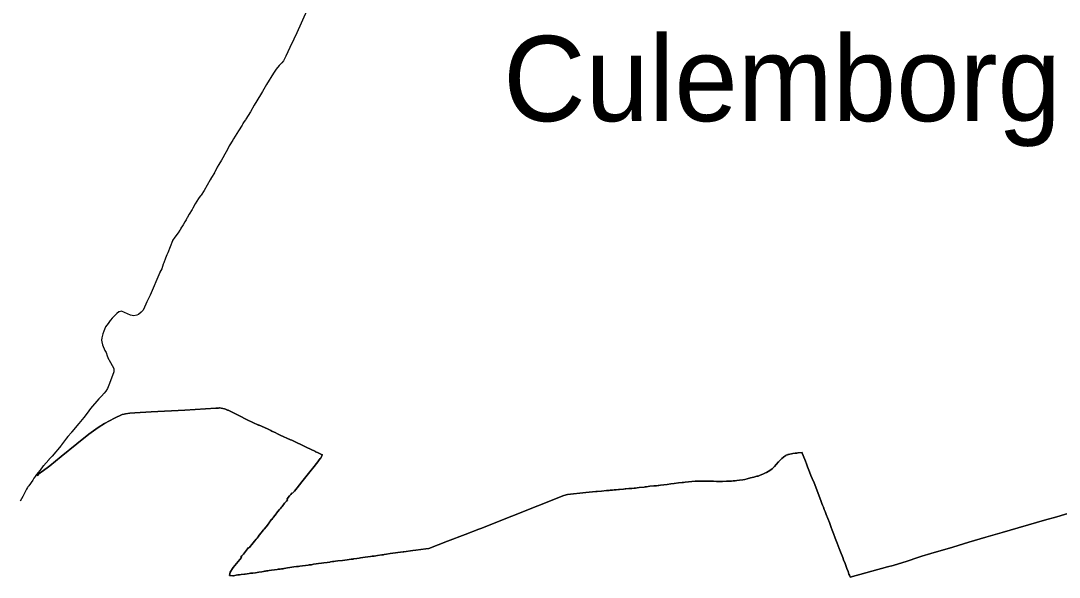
# Model space of a CAD drawing. Extents: x 113371 to 291721, y 393993 to 520143.
# Drawn here: x 138045 to 144134, y 436828 to 440092 of the extents above; entities that cross this region are included whole.
import ezdxf

# ---------------------------------------------------------------- set-up
doc = ezdxf.new("R2010")
doc.units = 0
doc.layers.add('Default', color=7, linetype='Continuous')
doc.layers.add('plaatsnamen', color=7, linetype='Continuous')

msp = doc.modelspace()

# ---------------------------------------------------------------- linework, layer by layer
at = {"layer": 'Default'}
for points in [[(139722.235625, 440152.3025), (139662.915625, 440021.2725), (139645.085625, 439984.0625), (139622.425625, 439935.0425), (139599.285625, 439884.5025), (139589.075625, 439864.6125), (139584.495625, 439857.6125), (139576.305625, 439845.1125), (139573.485625, 439843.1825), (139569.165625, 439840.2225), (139559.865625, 439830.6425), (139542.355625, 439808.3625), (139526.855625, 439785.1325), (139486.425625, 439718.1125), (139462.005625, 439677.6425), (139450.355625, 439658.4625), (139413.485625, 439597.7025), (139391.145625, 439558.9425), (139365.325625, 439514.1325), (139363.095625, 439510.2725), (139355.395625, 439500.4825), (139347.825625, 439488.7225), (139347.305625, 439487.7525), (139343.085625, 439479.8825), (139322.325625, 439445.6325), (139292.015625, 439399.2025), (139291.255625, 439397.6825), (139287.845625, 439390.9925), (139267.355625, 439357.7225), (139260.695625, 439345.0625), (139249.415625, 439323.5825)], [(139249.415625, 439323.5825), (139241.105625, 439309.1525), (139229.465625, 439288.9325), (139221.445625, 439274.9925), (139205.915625, 439248.5725), (139197.465625, 439234.1825), (139183.105625, 439205.0225), (139181.465625, 439202.3325), (139180.005625, 439199.9625), (139162.875625, 439172.0725), (139161.585625, 439169.9725), (139160.625625, 439168.4325), (139154.835625, 439158.2925), (139137.505625, 439127.9725), (139119.505625, 439097.3625), (139101.915625, 439069.7725), (139098.095625, 439064.9125), (139090.885625, 439054.6225), (139087.955625, 439049.0825), (139077.005625, 439033.2525), (139067.215625, 439018.0925), (139054.615625, 438992.8825), (139049.145625, 438984.5825), (139032.805625, 438958.2025), (139020.945625, 438936.4125), (139019.385625, 438933.3925), (139014.325625, 438925.1925), (139006.725625, 438912.4925), (138996.595625, 438896.1525), (138988.945625, 438883.4525), (138987.685625, 438881.3525), (138984.035625, 438875.2125), (138983.805625, 438874.7425), (138983.255625, 438873.8225), (138978.765625, 438864.5025), (138978.615625, 438864.1925), (138978.325625, 438863.6125), (138967.695625, 438848.6625)], [(138967.695625, 438848.6625), (138949.055625, 438822.4525), (138934.825625, 438802.4325), (138934.755625, 438802.2725), (138906.345625, 438731.2225), (138901.775625, 438719.2025), (138901.455625, 438718.3525), (138894.315625, 438699.6225), (138883.985625, 438672.5125), (138880.695625, 438663.8825), (138871.095625, 438637.9325), (138861.275625, 438617.9325), (138861.105625, 438617.5825), (138860.285625, 438615.6725), (138803.145625, 438483.4925), (138784.915625, 438443.9025), (138784.385625, 438442.7425), (138778.765625, 438430.5425), (138778.755625, 438430.5225), (138778.535625, 438430.0425), (138761.915625, 438393.9325), (138750.095625, 438383.0225), (138735.325625, 438369.3625), (138725.695625, 438364.9125), (138708.335625, 438361.4125), (138687.755625, 438366.2725), (138636.075625, 438389.1625), (138622.285625, 438384.5725), (138620.575625, 438383.9925), (138608.915625, 438374.7725), (138580.305625, 438346.8925), (138571.265625, 438336.5125), (138569.625625, 438334.6325), (138556.445625, 438316.5725), (138542.145625, 438296.9725), (138536.465625, 438282.1725), (138532.325625, 438271.3825), (138526.355625, 438255.8225)], [(138526.355625, 438255.8225), (138520.395625, 438232.2525), (138519.195625, 438219.2725), (138521.035625, 438209.6325), (138524.445625, 438191.6125), (138524.675625, 438191.0225), (138536.965625, 438158.2925), (138545.735625, 438146.9025), (138551.865625, 438126.7225), (138559.645625, 438107.7225), (138560.545625, 438106.1625), (138591.595625, 438052.3825), (138589.825625, 438032.7525), (138582.285625, 438011.5425), (138561.915625, 437954.2525), (138553.575625, 437935.1125), (138544.325625, 437920.0625), (138533.175625, 437906.9725), (138518.395625, 437889.6125), (138502.835625, 437873.5425), (138454.415625, 437817.1625), (138433.285625, 437789.7025), (138413.945625, 437764.5825), (138385.055625, 437730.5725), (138344.185625, 437680.4725), (138342.955625, 437678.0425), (138342.395625, 437676.9325), (138320.805625, 437653.1125), (138313.225625, 437643.0025), (138284.565625, 437604.7825), (138282.215625, 437601.6325), (138228.385625, 437538.4425), (138226.775625, 437536.5525), (138210.275625, 437518.2425), (138209.035625, 437516.8625), (138178.165625, 437480.7225), (138177.075625, 437481.6125), (138176.585625, 437480.9525)], [(138176.585625, 437480.9525), (138158.185625, 437456.6125), (138157.015625, 437455.0625), (138146.125625, 437442.5225), (138137.345625, 437430.4325), (138137.865625, 437430.1825), (138145.485625, 437425.4525), (138147.875625, 437427.5725), (138147.905625, 437430.2225), (138160.825625, 437443.1125), (138170.195625, 437447.5225), (138216.025625, 437482.0825), (138281.535625, 437535.3325), (138374.445625, 437611.1125), (138444.845625, 437667.4425), (138498.095625, 437705.8525), (138536.495625, 437729.3625), (138594.845625, 437760.8025), (138640.165625, 437781.9125), (138650.845625, 437784.1325), (138659.835625, 437786.9425), (138683.755625, 437790.5025), (138713.755625, 437791.8525), (138809.415625, 437798.8325), (139007.705625, 437809.0025), (139187.895625, 437819.0925), (139204.445625, 437819.1025), (139208.455625, 437821.3325), (139209.285625, 437821.7925), (139230.665625, 437817.7825), (139239.525625, 437814.9325), (139245.135625, 437814.5225), (139246.215625, 437814.0425), (139253.365625, 437810.3525), (139256.185625, 437808.8925), (139260.295625, 437807.1125), (139276.165625, 437800.6825), (139281.175625, 437798.4325)], [(139491.545625, 437697.6225), (139442.755625, 437719.3925), (139439.575625, 437720.6925), (139437.445625, 437721.5725), (139435.355625, 437722.4325), (139431.465625, 437724.0325), (139414.035625, 437731.4925), (139397.975625, 437738.9425), (139397.605625, 437739.1125), (139381.145625, 437746.7125), (139379.335625, 437747.5025), (139377.305625, 437748.4125), (139319.735625, 437779.1925), (139319.025625, 437779.5425), (139307.485625, 437785.1825), (139292.375625, 437792.9425), (139284.035625, 437797.0325), (139281.175625, 437798.4325), (139276.165625, 437800.6825), (139260.295625, 437807.1125), (139256.185625, 437808.8925), (139253.365625, 437810.3525), (139246.215625, 437814.0425), (139245.135625, 437814.5225), (139239.525625, 437814.9325), (139230.665625, 437817.7825), (139209.285625, 437821.7925), (139208.455625, 437821.3325), (139204.445625, 437819.1025), (139187.895625, 437819.0925), (139007.705625, 437809.0025), (138809.415625, 437798.8325), (138713.755625, 437791.8525), (138683.755625, 437790.5025), (138659.835625, 437786.9425), (138650.845625, 437784.1325), (138640.165625, 437781.9125), (138594.845625, 437760.8025)], [(138594.845625, 437760.8025), (138536.495625, 437729.3625), (138498.095625, 437705.8525), (138444.845625, 437667.4425), (138374.445625, 437611.1125), (138281.535625, 437535.3325), (138216.025625, 437482.0825), (138170.195625, 437447.5225), (138160.825625, 437443.1125), (138147.905625, 437430.2225), (138147.875625, 437427.5725), (138145.485625, 437425.4525), (138137.865625, 437430.1825), (138137.345625, 437430.4325), (138137.275625, 437430.3425), (138131.435625, 437422.1825), (138131.275625, 437421.9625), (138131.105625, 437421.7325), (138122.325625, 437409.6425), (138116.915625, 437400.3925), (138114.705625, 437397.2925), (138091.295625, 437364.3625), (138087.195625, 437358.5925), (138084.415625, 437354.6825), (138077.715625, 437343.8825), (138068.305625, 437325.3625), (138057.015625, 437300.8825), (138041.445625, 437274.9325)], [(139281.175625, 437798.4325), (139284.035625, 437797.0325), (139292.375625, 437792.9425), (139307.485625, 437785.1825), (139319.025625, 437779.5425), (139319.735625, 437779.1925), (139377.305625, 437748.4125), (139379.335625, 437747.5025), (139381.145625, 437746.7125), (139397.605625, 437739.1125), (139397.975625, 437738.9425), (139414.035625, 437731.4925), (139431.465625, 437724.0325), (139435.355625, 437722.4325), (139437.445625, 437721.5725), (139439.575625, 437720.6925), (139442.755625, 437719.3925), (139491.545625, 437697.6225), (139506.805625, 437690.8125), (139510.845625, 437688.5725), (139517.675625, 437685.1825), (139520.875625, 437683.5925), (139536.375625, 437676.4325), (139550.415625, 437669.4525), (139566.475625, 437661.5825), (139626.365625, 437633.0525), (139626.525625, 437633.0325), (139634.275625, 437631.6625), (139635.235625, 437631.1825), (139718.195625, 437590.4525), (139772.165625, 437565.1125), (139773.975625, 437564.2525), (139784.775625, 437559.1825), (139808.905625, 437547.8525), (139813.645625, 437545.6325), (139810.985625, 437541.3925), (139810.465625, 437540.5625), (139807.645625, 437536.0525)], [(139607.305625, 437287.3425), (139621.485625, 437304.9725), (139628.365625, 437314.0825), (139634.125625, 437321.8425), (139635.395625, 437323.4125), (139638.885625, 437320.4225), (139647.175625, 437330.0325), (139649.065625, 437332.0725), (139665.285625, 437351.8625), (139692.975625, 437387.7525), (139716.715625, 437417.1825), (139748.395625, 437456.6925), (139757.735625, 437468.6125), (139786.585625, 437505.1125), (139791.395625, 437511.2125), (139801.375625, 437524.3725), (139803.445625, 437526.6125), (139807.645625, 437536.0525), (139810.465625, 437540.5625), (139810.985625, 437541.3925), (139813.645625, 437545.6325), (139808.905625, 437547.8525), (139784.775625, 437559.1825), (139773.975625, 437564.2525), (139772.165625, 437565.1125), (139718.195625, 437590.4525), (139635.235625, 437631.1825), (139634.275625, 437631.6625), (139626.525625, 437633.0325), (139626.365625, 437633.0525), (139566.475625, 437661.5825), (139550.415625, 437669.4525), (139536.375625, 437676.4325), (139520.875625, 437683.5925), (139517.675625, 437685.1825), (139510.845625, 437688.5725), (139506.805625, 437690.8125), (139491.545625, 437697.6225)], [(139807.645625, 437536.0525), (139803.445625, 437526.6125), (139801.375625, 437524.3725), (139791.395625, 437511.2125), (139786.585625, 437505.1125), (139757.735625, 437468.6125), (139748.395625, 437456.6925), (139716.715625, 437417.1825), (139692.975625, 437387.7525), (139665.285625, 437351.8625), (139649.065625, 437332.0725), (139647.175625, 437330.0325), (139638.885625, 437320.4225), (139635.395625, 437323.4125), (139634.125625, 437321.8425), (139628.365625, 437314.0825), (139621.485625, 437304.9725), (139607.305625, 437287.3425), (139606.595625, 437286.3925), (139608.835625, 437282.5825), (139602.235625, 437274.6825), (139602.185625, 437274.6225), (139596.695625, 437267.7525), (139591.995625, 437261.8825), (139577.715625, 437243.8125), (139573.885625, 437239.3925), (139568.105625, 437231.9025), (139562.985625, 437225.5525), (139551.225625, 437211.0725), (139535.805625, 437191.5125), (139525.465625, 437179.0125), (139522.705625, 437175.0525), (139520.795625, 437172.4325), (139516.515625, 437167.0825), (139515.735625, 437166.0625), (139507.735625, 437155.9225), (139505.685625, 437153.3725), (139499.325625, 437144.7025)], [(142203.435625, 437391.3625), (142213.025625, 437392.4925), (142222.935625, 437392.9225), (142233.605625, 437393.7325), (142244.365625, 437395.3525), (142259.665625, 437397.1425), (142278.085625, 437399.4025), (142289.815625, 437401.6825), (142304.275625, 437405.3025), (142324.045625, 437410.4225), (142342.505625, 437415.3525), (142354.475625, 437418.1525), (142361.195625, 437420.1125), (142364.805625, 437420.7525), (142367.985625, 437421.3725), (142371.935625, 437422.7125), (142380.815625, 437426.0125), (142395.505625, 437432.9025), (142400.435625, 437434.9025), (142411.655625, 437440.6025), (142417.015625, 437443.2525), (142427.765625, 437448.7425), (142437.885625, 437454.9625), (142449.855625, 437463.1625), (142457.545625, 437470.4825), (142464.255625, 437477.9625), (142474.155625, 437488.5625), (142488.775625, 437504.3625), (142499.865625, 437516.0325), (142508.345625, 437525.0625), (142516.575625, 437532.7825), (142519.915625, 437535.1825), (142530.675625, 437542.9625), (142532.355625, 437543.9625), (142533.615625, 437544.3725), (142540.305625, 437546.2925), (142543.435625, 437547.6525), (142546.315625, 437548.3625)], [(142742.695625, 437261.3225), (142736.025625, 437278.7425), (142696.125625, 437380.9325), (142684.425625, 437407.4425), (142677.495625, 437425.1025), (142669.885625, 437446.0125), (142658.455625, 437475.9625), (142651.615625, 437493.7425), (142645.765625, 437507.9925), (142632.375625, 437541.3725), (142627.355625, 437556.4925), (142626.215625, 437559.4125), (142602.785625, 437557.0025), (142600.735625, 437556.8625), (142595.775625, 437556.1525), (142585.595625, 437554.9725), (142572.625625, 437553.4425), (142564.075625, 437552.0825), (142553.895625, 437550.2225), (142546.315625, 437548.3625), (142543.435625, 437547.6525), (142540.305625, 437546.2925), (142533.615625, 437544.3725), (142532.355625, 437543.9625), (142530.675625, 437542.9625), (142519.915625, 437535.1825), (142516.575625, 437532.7825), (142508.345625, 437525.0625), (142499.865625, 437516.0325), (142488.775625, 437504.3625), (142474.155625, 437488.5625), (142464.255625, 437477.9625), (142457.545625, 437470.4825), (142449.855625, 437463.1625), (142437.885625, 437454.9625), (142427.765625, 437448.7425), (142417.015625, 437443.2525), (142411.655625, 437440.6025)], [(142546.315625, 437548.3625), (142553.895625, 437550.2225), (142564.075625, 437552.0825), (142572.625625, 437553.4425), (142585.595625, 437554.9725), (142595.775625, 437556.1525), (142600.735625, 437556.8625), (142602.785625, 437557.0025), (142626.215625, 437559.4125), (142627.355625, 437556.4925), (142632.375625, 437541.3725), (142645.765625, 437507.9925), (142651.615625, 437493.7425), (142658.455625, 437475.9625), (142669.885625, 437446.0125), (142677.495625, 437425.1025), (142684.425625, 437407.4425), (142696.125625, 437380.9325), (142736.025625, 437278.7425), (142742.695625, 437261.3225), (142746.695625, 437250.8225), (142751.195625, 437239.1625), (142756.565625, 437225.3425), (142761.085625, 437213.6025), (142768.175625, 437195.4725), (142786.335625, 437149.4425), (142794.625625, 437124.7725), (142796.695625, 437119.5525), (142802.605625, 437104.0225), (142810.345625, 437084.0925), (142820.955625, 437056.4725), (142831.845625, 437028.6725), (142838.715625, 437011.4025), (142844.505625, 436996.8525), (142851.935625, 436977.4925), (142864.375625, 436944.6225), (142869.725625, 436930.6425), (142877.945625, 436908.3525)], [(142411.655625, 437440.6025), (142400.435625, 437434.9025), (142395.505625, 437432.9025), (142380.815625, 437426.0125), (142371.935625, 437422.7125), (142367.985625, 437421.3725), (142364.805625, 437420.7525), (142361.195625, 437420.1125), (142354.475625, 437418.1525), (142342.505625, 437415.3525), (142324.045625, 437410.4225), (142304.275625, 437405.3025), (142289.815625, 437401.6825), (142278.085625, 437399.4025), (142259.665625, 437397.1425), (142244.365625, 437395.3525), (142233.605625, 437393.7325), (142222.935625, 437392.9225), (142213.025625, 437392.4925), (142203.435625, 437391.3625), (142195.815625, 437390.9525), (142191.535625, 437390.9525), (142185.965625, 437390.8225), (142183.325625, 437390.8925), (142158.715625, 437390.1825), (142157.475625, 437390.0425), (142152.665625, 437390.0525), (142143.765625, 437390.1025), (142125.085625, 437390.0425), (142106.675625, 437390.6325), (142076.945625, 437391.6525), (142069.865625, 437391.9825), (142050.735625, 437391.9625), (142031.325625, 437391.6325), (142013.855625, 437391.4425), (141999.255625, 437391.0425), (141979.495625, 437389.4925), (141960.825625, 437387.7725)], [(141960.825625, 437387.7725), (141941.125625, 437385.6125), (141931.535625, 437384.3825), (141922.255625, 437382.9625), (141901.615625, 437380.9525), (141876.915625, 437377.9225), (141857.465625, 437375.9825), (141834.155625, 437372.6925), (141816.155625, 437370.3025), (141796.975625, 437368.0525), (141785.935625, 437366.5125), (141781.745625, 437365.7925), (141773.055625, 437364.8025), (141756.715625, 437363.2325), (141733.425625, 437361.3725), (141713.365625, 437359.0025), (141705.695625, 437357.4325), (141699.305625, 437356.7025), (141670.205625, 437353.4125), (141659.475625, 437351.9925), (141649.175625, 437351.1125), (141641.715625, 437350.7025), (141627.125625, 437349.2925), (141610.085625, 437347.8025), (141592.815625, 437346.1825), (141588.185625, 437346.0125), (141578.275625, 437345.4925), (141556.185625, 437343.0025), (141550.505625, 437342.6325), (141536.765625, 437341.5725), (141524.525625, 437340.4325), (141514.575625, 437339.2925), (141500.425625, 437338.0125), (141494.585625, 437337.4025), (141479.455625, 437335.8325), (141450.145625, 437333.1925), (141424.645625, 437330.9925), (141422.075625, 437330.7525)], [(141659.475625, 437351.9925), (141670.205625, 437353.4125), (141699.305625, 437356.7025), (141705.695625, 437357.4325), (141713.365625, 437359.0025), (141733.425625, 437361.3725), (141756.715625, 437363.2325), (141773.055625, 437364.8025), (141781.745625, 437365.7925), (141785.935625, 437366.5125), (141796.975625, 437368.0525), (141816.155625, 437370.3025), (141834.155625, 437372.6925), (141857.465625, 437375.9825), (141876.915625, 437377.9225), (141901.615625, 437380.9525), (141922.255625, 437382.9625), (141931.535625, 437384.3825), (141941.125625, 437385.6125), (141960.825625, 437387.7725), (141979.495625, 437389.4925), (141999.255625, 437391.0425), (142013.855625, 437391.4425), (142031.325625, 437391.6325), (142050.735625, 437391.9625), (142069.865625, 437391.9825), (142076.945625, 437391.6525), (142106.675625, 437390.6325), (142125.085625, 437390.0425), (142143.765625, 437390.1025), (142152.665625, 437390.0525), (142157.475625, 437390.0425), (142158.715625, 437390.1825), (142183.325625, 437390.8925), (142185.965625, 437390.8225), (142191.535625, 437390.9525), (142195.815625, 437390.9525), (142203.435625, 437391.3625)], [(141422.075625, 437330.7525), (141417.765625, 437330.3725), (141357.755625, 437324.9825), (141250.015625, 437313.3225), (141228.905625, 437308.0425), (140772.325625, 437126.5325), (140747.615625, 437116.6025), (140730.645625, 437109.7625), (140651.455625, 437078.7925), (140547.495625, 437039.6925), (140438.205625, 436996.5625), (140419.785625, 436993.6625), (140361.615625, 436986.4325), (140344.075625, 436984.2225), (140290.125625, 436977.4225), (140287.595625, 436977.1025), (140210.325625, 436966.9425), (140189.515625, 436963.3325), (140176.135625, 436961.0125), (140171.755625, 436960.2525), (140162.985625, 436958.7425), (140162.825625, 436958.7125), (140136.965625, 436955.1225), (140117.115625, 436952.1425), (140111.925625, 436951.2725), (140110.145625, 436951.3425), (140104.545625, 436950.8425), (140096.035625, 436949.5725), (140064.715625, 436945.2225), (140037.725625, 436942.0425), (140029.215625, 436940.6525), (140028.935625, 436940.6125), (140015.515625, 436938.2325), (139998.415625, 436935.8825), (139995.015625, 436935.3325), (139994.735625, 436934.9625), (139982.405625, 436933.4725), (139959.305625, 436930.2725)], [(140171.755625, 436960.2525), (140176.135625, 436961.0125), (140189.515625, 436963.3325), (140210.325625, 436966.9425), (140287.595625, 436977.1025), (140290.125625, 436977.4225), (140344.075625, 436984.2225), (140361.615625, 436986.4325), (140419.785625, 436993.6625), (140438.205625, 436996.5625), (140547.495625, 437039.6925), (140651.455625, 437078.7925), (140730.645625, 437109.7625), (140747.615625, 437116.6025), (140772.325625, 437126.5325), (141228.905625, 437308.0425), (141250.015625, 437313.3225), (141357.755625, 437324.9825), (141417.765625, 437330.3725), (141422.075625, 437330.7525), (141424.645625, 437330.9925), (141450.145625, 437333.1925), (141479.455625, 437335.8325), (141494.585625, 437337.4025), (141500.425625, 437338.0125), (141514.575625, 437339.2925), (141524.525625, 437340.4325), (141536.765625, 437341.5725), (141550.505625, 437342.6325), (141556.185625, 437343.0025), (141578.275625, 437345.4925), (141588.185625, 437346.0125), (141592.815625, 437346.1825), (141610.085625, 437347.8025), (141627.125625, 437349.2925), (141641.715625, 437350.7025), (141649.175625, 437351.1125), (141659.475625, 437351.9925)], [(139380.675625, 437001.4925), (139383.135625, 437000.2525), (139385.665625, 437003.3325), (139390.085625, 437008.4525), (139399.575625, 437020.4025), (139414.975625, 437039.1625), (139425.355625, 437051.2025), (139429.915625, 437056.0025), (139430.665625, 437057.0525), (139436.515625, 437065.1325), (139443.095625, 437074.4525), (139454.715625, 437088.5725), (139460.985625, 437096.6725), (139468.625625, 437105.6625), (139472.325625, 437110.4825), (139483.205625, 437123.8525), (139497.255625, 437141.9825), (139499.325625, 437144.7025), (139505.685625, 437153.3725), (139507.735625, 437155.9225), (139515.735625, 437166.0625), (139516.515625, 437167.0825), (139520.795625, 437172.4325), (139522.705625, 437175.0525), (139525.465625, 437179.0125), (139535.805625, 437191.5125), (139551.225625, 437211.0725), (139562.985625, 437225.5525), (139568.105625, 437231.9025), (139573.885625, 437239.3925), (139577.715625, 437243.8125), (139591.995625, 437261.8825), (139596.695625, 437267.7525), (139602.185625, 437274.6225), (139602.235625, 437274.6825), (139608.835625, 437282.5825), (139606.595625, 437286.3925), (139607.305625, 437287.3425)], [(144048.015625, 437162.7725), (143799.615625, 437090.2725), (143704.425625, 437063.7225), (143603.325625, 437032.9225), (143509.605625, 437003.6325), (143381.255625, 436967.6225), (143328.245625, 436952.1125), (143286.705625, 436938.0725), (143259.005625, 436928.5125), (143236.205625, 436919.9425), (143216.565625, 436913.9625), (143159.305625, 436897.5825), (143127.295625, 436888.9825), (142908.145625, 436827.9725), (142907.615625, 436829.3925), (142903.695625, 436840.0925), (142900.965625, 436846.4025), (142895.605625, 436860.7025), (142888.835625, 436880.1525), (142877.945625, 436908.3525), (142869.725625, 436930.6425), (142864.375625, 436944.6225), (142851.935625, 436977.4925), (142844.505625, 436996.8525), (142838.715625, 437011.4025), (142831.845625, 437028.6725), (142820.955625, 437056.4725), (142810.345625, 437084.0925), (142802.605625, 437104.0225), (142796.695625, 437119.5525), (142794.625625, 437124.7725), (142786.335625, 437149.4425), (142768.175625, 437195.4725), (142761.085625, 437213.6025), (142756.565625, 437225.3425), (142751.195625, 437239.1625), (142746.695625, 437250.8225), (142742.695625, 437261.3225)], [(142877.945625, 436908.3525), (142888.835625, 436880.1525), (142895.605625, 436860.7025), (142900.965625, 436846.4025), (142903.695625, 436840.0925), (142907.615625, 436829.3925), (142908.145625, 436827.9725), (143127.295625, 436888.9825), (143159.305625, 436897.5825), (143216.565625, 436913.9625), (143236.205625, 436919.9425), (143259.005625, 436928.5125), (143286.705625, 436938.0725), (143328.245625, 436952.1125), (143381.255625, 436967.6225), (143509.605625, 437003.6325), (143603.325625, 437032.9225), (143704.425625, 437063.7225), (143799.615625, 437090.2725), (144048.015625, 437162.7725), (144119.155625, 437182.8025), (144208.925625, 437210.3025)], [(144208.925625, 437210.3025), (144119.155625, 437182.8025), (144048.015625, 437162.7725)], [(139499.325625, 437144.7025), (139497.255625, 437141.9825), (139483.205625, 437123.8525), (139472.325625, 437110.4825), (139468.625625, 437105.6625), (139460.985625, 437096.6725), (139454.715625, 437088.5725), (139443.095625, 437074.4525), (139436.515625, 437065.1325), (139430.665625, 437057.0525), (139429.915625, 437056.0025), (139425.355625, 437051.2025), (139414.975625, 437039.1625), (139399.575625, 437020.4025), (139390.085625, 437008.4525), (139385.665625, 437003.3325), (139383.135625, 437000.2525), (139380.675625, 437001.4925), (139350.755625, 436963.9625), (139344.015625, 436955.5125), (139341.755625, 436952.6625), (139335.985625, 436945.4325), (139338.445625, 436943.5025), (139289.755625, 436885.1325), (139272.925625, 436858.2925), (139268.325625, 436838.0425), (139268.575625, 436838.0225), (139288.575625, 436836.3125), (139290.515625, 436836.5825), (139292.935625, 436836.9325), (139308.695625, 436840.3825), (139316.735625, 436841.5125), (139321.175625, 436841.9825), (139324.665625, 436842.2925), (139326.235625, 436842.4725), (139326.935625, 436842.4925)], [(139514.785625, 436868.9925), (139501.965625, 436867.0925), (139494.205625, 436866.0225), (139485.475625, 436864.8325), (139480.255625, 436864.1325), (139476.595625, 436863.5725), (139474.735625, 436863.2625), (139467.245625, 436861.8925), (139457.725625, 436860.4525), (139441.485625, 436857.7725), (139421.875625, 436854.6925), (139404.845625, 436852.4725), (139401.035625, 436852.1125), (139392.855625, 436851.0525), (139383.385625, 436849.8825), (139361.515625, 436846.7725), (139358.185625, 436846.0225), (139356.585625, 436845.5225), (139338.185625, 436843.6725), (139326.935625, 436842.4925), (139326.235625, 436842.4725), (139324.665625, 436842.2925), (139321.175625, 436841.9825), (139316.735625, 436841.5125), (139308.695625, 436840.3825), (139292.935625, 436836.9325), (139290.515625, 436836.5825), (139288.575625, 436836.3125), (139268.575625, 436838.0225), (139268.325625, 436838.0425), (139272.925625, 436858.2925), (139289.755625, 436885.1325), (139338.445625, 436943.5025), (139335.985625, 436945.4325), (139341.755625, 436952.6625), (139344.015625, 436955.5125), (139350.755625, 436963.9625), (139380.675625, 437001.4925)], [(139715.225625, 436897.5225), (139729.505625, 436899.5825), (139735.945625, 436900.5925), (139737.615625, 436900.7325), (139749.035625, 436901.6525), (139761.195625, 436903.7225), (139777.345625, 436906.3025), (139791.125625, 436908.3125), (139807.755625, 436910.5425), (139822.565625, 436912.5425), (139840.725625, 436914.9725), (139857.075625, 436917.2825), (139861.895625, 436918.1125), (139873.175625, 436919.3625), (139881.165625, 436920.3925), (139891.015625, 436921.3025), (139903.675625, 436923.2925), (139932.105625, 436926.1125), (139944.865625, 436927.5225), (139959.305625, 436930.2725), (139982.405625, 436933.4725), (139994.735625, 436934.9625), (139995.015625, 436935.3325), (139998.415625, 436935.8825), (140015.515625, 436938.2325), (140028.935625, 436940.6125), (140029.215625, 436940.6525), (140037.725625, 436942.0425), (140064.715625, 436945.2225), (140096.035625, 436949.5725), (140104.545625, 436950.8425), (140110.145625, 436951.3425), (140111.925625, 436951.2725), (140117.115625, 436952.1425), (140136.965625, 436955.1225), (140162.825625, 436958.7125), (140162.985625, 436958.7425), (140171.755625, 436960.2525)], [(139326.935625, 436842.4925), (139338.185625, 436843.6725), (139356.585625, 436845.5225), (139358.185625, 436846.0225), (139361.515625, 436846.7725), (139383.385625, 436849.8825), (139392.855625, 436851.0525), (139401.035625, 436852.1125), (139404.845625, 436852.4725), (139421.875625, 436854.6925), (139441.485625, 436857.7725), (139457.725625, 436860.4525), (139467.245625, 436861.8925), (139474.735625, 436863.2625), (139476.595625, 436863.5725), (139480.255625, 436864.1325), (139485.475625, 436864.8325), (139494.205625, 436866.0225), (139501.965625, 436867.0925), (139514.785625, 436868.9925), (139533.095625, 436871.4925), (139547.855625, 436873.7125), (139554.395625, 436874.5525), (139562.185625, 436875.4025), (139566.485625, 436875.8625), (139573.765625, 436876.4925), (139582.685625, 436877.9325), (139587.015625, 436878.5425), (139589.915625, 436878.9825), (139598.185625, 436880.7225), (139608.395625, 436882.5325), (139623.425625, 436884.8225), (139646.715625, 436888.4525), (139661.275625, 436890.2825), (139673.275625, 436891.7425), (139680.465625, 436892.4925), (139696.975625, 436895.3025), (139715.225625, 436897.5225)], [(139959.305625, 436930.2725), (139944.865625, 436927.5225), (139932.105625, 436926.1125), (139903.675625, 436923.2925), (139891.015625, 436921.3025), (139881.165625, 436920.3925), (139873.175625, 436919.3625), (139861.895625, 436918.1125), (139857.075625, 436917.2825), (139840.725625, 436914.9725), (139822.565625, 436912.5425), (139807.755625, 436910.5425), (139791.125625, 436908.3125), (139777.345625, 436906.3025), (139761.195625, 436903.7225), (139749.035625, 436901.6525), (139737.615625, 436900.7325), (139735.945625, 436900.5925), (139729.505625, 436899.5825), (139715.225625, 436897.5225), (139696.975625, 436895.3025), (139680.465625, 436892.4925), (139673.275625, 436891.7425), (139661.275625, 436890.2825), (139646.715625, 436888.4525), (139623.425625, 436884.8225), (139608.395625, 436882.5325), (139598.185625, 436880.7225), (139589.915625, 436878.9825), (139587.015625, 436878.5425), (139582.685625, 436877.9325), (139573.765625, 436876.4925), (139566.485625, 436875.8625), (139562.185625, 436875.4025), (139554.395625, 436874.5525), (139547.855625, 436873.7125), (139533.095625, 436871.4925), (139514.785625, 436868.9925)]]:
    msp.add_lwpolyline(points, dxfattribs=at)

# ---------------------------------------------------------------- texts
at = {"layer": 'plaatsnamen'}
msp.add_text('Culemborg', height=500, dxfattribs=at).set_placement((140873.847041, 439503.403519))

doc.saveas('drawing.dxf')
